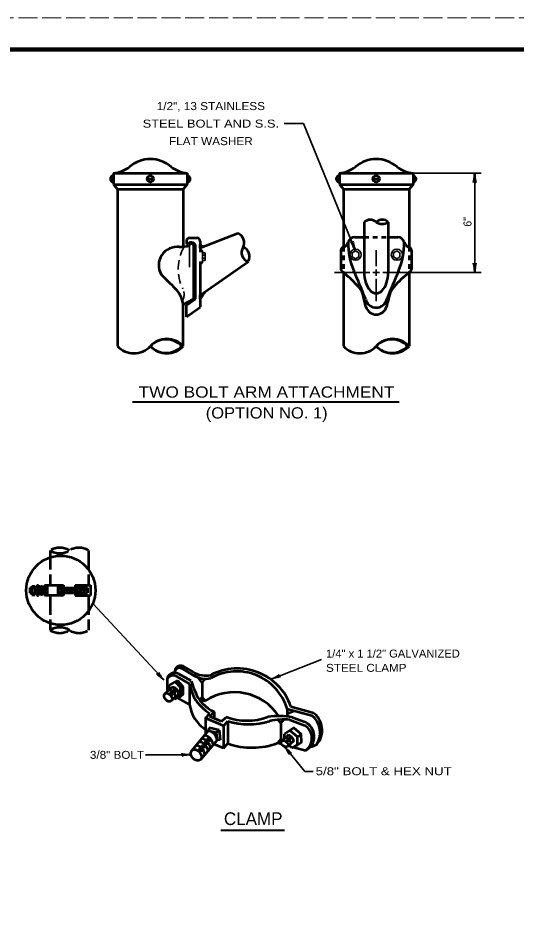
# Model space of a CAD drawing. Extents: x 6488 to 7168, y 276 to 716.
# Drawn here: x 6645 to 6801.8, y 436 to 716 of the extents above; entities that cross this region are included whole.
import ezdxf
from ezdxf.enums import TextEntityAlignment as Align

# ---------------------------------------------------------------- set-up
doc = ezdxf.new("R2010")
doc.units = 0
for name, pattern in [('LONG_DASHED', [7.5, 6, -1.5]), ('MEDIUM_DASHED', [4.5, 3, -1.5]), ('SHORT_DASHED', [2.7, 1.5, -1.2])]:
    doc.linetypes.add(name, pattern=pattern)
doc.layers.add('1', color=7, linetype='Continuous', lineweight=35)
doc.layers.add('61', color=7, linetype='Continuous', lineweight=35)

msp = doc.modelspace()

# ---------------------------------------------------------------- linework, layer by layer
at = {"layer": '1'}
for p, q in [((6728.799, 682.801), (6734.872, 682.801)), ((6751.122, 642.92), (6734.872, 682.801)), ((6769.322, 667.1), (6790.742, 667.1)), ((6788.742, 667.1), (6788.742, 635.86)), ((6698.982, 637.52), (6698.982, 644.38)), ((6700.122, 627.44), (6700.122, 644.06)), ((6703.122, 639.08), (6703.122, 642.44)), ((6751.242, 642.68), (6750.222, 642.06)), ((6750.222, 642.06), (6750.222, 640.8)), ((6751.242, 642.68), (6752.242, 642.06)), ((6752.242, 642.06), (6752.242, 640.8)), ((6757.742, 642.92), (6757.742, 637.86)), ((6764.222, 642.68), (6763.222, 642.06)), ((6763.222, 642.06), (6763.222, 640.8)), ((6764.222, 642.68), (6765.222, 642.06)), ((6765.222, 642.06), (6765.222, 640.8)), ((6703.882, 641.26), (6703.142, 641.26)), ((6703.882, 640.4), (6703.142, 640.4)), ((6703.882, 639.66), (6703.142, 639.66)), ((6744.642, 635.86), (6755.742, 635.86)), ((6756.702, 635.86), (6758.722, 635.86)), ((6757.742, 636.84), (6757.742, 634.84)), ((6759.782, 635.86), (6790.742, 635.86)), ((6757.742, 633.82), (6757.742, 626.78)), ((6668.533, 531.678), (6690.869, 507.577)), ((6724.751, 507.828), (6740.562, 513.979)), ((6699.435, 483.978), (6685.097, 483.978))]:
    msp.add_line(p, q, dxfattribs=at)
at = {"layer": '1', "lineweight": 53}
for p, q in [((6675.082, 667.1), (6698.262, 667.1)), ((6675.082, 667.1), (6675.082, 663.58)), ((6698.262, 667.1), (6698.262, 663.58)), ((6746.142, 667.1), (6769.322, 667.1)), ((6746.142, 667.1), (6746.142, 663.58)), ((6769.322, 667.1), (6769.322, 663.58)), ((6674.082, 665.34), (6674.822, 665.34)), ((6685.902, 665.34), (6687.422, 665.34)), ((6698.522, 665.34), (6699.222, 665.34)), ((6745.142, 665.34), (6745.902, 665.34)), ((6756.982, 665.34), (6758.482, 665.34)), ((6769.582, 665.34), (6770.282, 665.34)), ((6675.082, 663.58), (6698.262, 663.58)), ((6675.082, 663.58), (6676.342, 662.06)), ((6676.342, 662.06), (6676.342, 612.68)), ((6676.342, 662.06), (6697.002, 662.06)), ((6698.262, 663.58), (6697.002, 662.06)), ((6697.002, 662.06), (6697.002, 643.92)), ((6746.142, 663.58), (6769.322, 663.58)), ((6746.142, 663.58), (6747.402, 662.06)), ((6747.402, 662.06), (6768.062, 662.06)), ((6747.402, 662.06), (6747.402, 643.92)), ((6769.322, 663.58), (6768.062, 662.06)), ((6768.062, 662.06), (6768.062, 643.92)), ((6753.962, 651.74), (6753.962, 635.86)), ((6761.522, 651.74), (6761.522, 635.86)), ((6702.362, 643.64), (6714.222, 648.18)), ((6750.882, 646.98), (6753.962, 646.98)), ((6761.522, 646.98), (6764.582, 646.98)), ((6698.022, 645.76), (6698.022, 644.72)), ((6698.022, 644.72), (6698.522, 644.72)), ((6699.022, 646.76), (6701.362, 646.76)), ((6702.362, 645.76), (6702.362, 645.24)), ((6702.362, 645.24), (6702.362, 642.2)), ((6700.902, 627.58), (6700.902, 643.76)), ((6746.642, 642.92), (6746.642, 636.86)), ((6768.822, 642.92), (6768.822, 636.86)), ((6702.362, 639.32), (6702.362, 629.74)), ((6702.362, 628.68), (6717.502, 639.28)), ((6747.402, 635.86), (6747.402, 612.68)), ((6768.062, 635.86), (6768.062, 612.68)), ((6697.002, 625.78), (6700.122, 627.44)), ((6698.022, 625.56), (6700.902, 627.58)), ((6702.362, 629.74), (6702.362, 624.9)), ((6697.002, 612.68), (6697.002, 625.78)), ((6698.022, 621.86), (6698.022, 625.56)), ((6698.022, 621.86), (6702.362, 624.9)), ((6648.782, 536.53), (6648.782, 535.01)), ((6648.782, 536.53), (6653.322, 536.53)), ((6648.782, 535.01), (6653.322, 535.01)), ((6649.082, 535.91), (6649.082, 535.61)), ((6649.382, 537.13), (6649.382, 534.41)), ((6649.382, 537.13), (6650.302, 537.13)), ((6650.302, 537.13), (6650.302, 534.41)), ((6650.902, 537.43), (6650.902, 534.11)), ((6650.902, 537.43), (6651.502, 537.43)), ((6651.502, 537.43), (6651.502, 534.11)), ((6652.122, 537.13), (6652.122, 534.41)), ((6652.122, 537.13), (6652.722, 537.13)), ((6652.722, 537.13), (6652.722, 534.41)), ((6653.322, 537.43), (6653.322, 534.11)), ((6653.322, 537.43), (6659.362, 537.43)), ((6654.222, 537.43), (6654.222, 534.11)), ((6657.562, 536.83), (6658.762, 536.83)), ((6657.562, 536.83), (6657.562, 534.71)), ((6657.862, 536.23), (6658.762, 536.23)), ((6657.862, 535.31), (6658.762, 535.31)), ((6658.762, 537.43), (6658.762, 534.11)), ((6659.362, 537.43), (6659.362, 534.11)), ((6659.822, 536.07), (6659.822, 535.47)), ((6660.282, 536.53), (6660.282, 535.01)), ((6660.722, 536.07), (6660.722, 535.47)), ((6661.182, 536.53), (6661.182, 535.01)), ((6661.642, 536.07), (6661.642, 535.47)), ((6662.102, 536.53), (6662.102, 535.01)), ((6662.542, 536.07), (6662.542, 535.47)), ((6663.002, 537.43), (6663.002, 534.11)), ((6663.002, 537.43), (6667.842, 537.43)), ((6663.602, 537.43), (6663.602, 534.11)), ((6664.822, 536.83), (6663.622, 536.83)), ((6664.522, 536.23), (6663.622, 536.23)), ((6664.522, 535.31), (6663.622, 535.31)), ((6664.822, 535.61), (6664.522, 535.31)), ((6664.522, 535.31), (6664.822, 535.01)), ((6664.822, 536.83), (6664.822, 534.71)), ((6665.342, 536.07), (6665.342, 535.47)), ((6665.882, 536.53), (6665.882, 535.01)), ((6666.402, 536.07), (6666.402, 535.47)), ((6666.922, 536.53), (6666.922, 535.01)), ((6667.842, 537.43), (6667.842, 534.11)), ((6649.382, 534.41), (6650.302, 534.41)), ((6650.902, 534.11), (6651.502, 534.11)), ((6652.722, 534.41), (6652.122, 534.41)), ((6659.362, 534.11), (6653.322, 534.11)), ((6657.562, 534.71), (6658.762, 534.71)), ((6663.002, 534.11), (6667.842, 534.11)), ((6664.822, 534.71), (6663.622, 534.71)), ((6700.179, 510.074), (6696.959, 511.914)), ((6700.179, 509.114), (6696.959, 510.934)), ((6691.919, 507.834), (6691.919, 503.814)), ((6695.259, 507.354), (6692.579, 505.934)), ((6694.499, 506.954), (6696.119, 505.154)), ((6699.039, 506.354), (6695.019, 508.654)), ((6699.539, 507.234), (6695.519, 509.514)), ((6702.979, 506.694), (6701.699, 508.334)), ((6702.979, 506.694), (6703.939, 507.934)), ((6693.479, 505.234), (6691.219, 503.194)), ((6692.579, 504.434), (6692.579, 505.934)), ((6699.039, 506.354), (6699.039, 499.794)), ((6695.499, 502.974), (6693.259, 500.954)), ((6694.099, 501.734), (6694.299, 501.494)), ((6699.039, 499.794), (6695.239, 501.954)), ((6702.979, 502.154), (6703.919, 500.974)), ((6702.499, 501.154), (6703.919, 500.974)), ((6729.699, 498.474), (6737.479, 496.374)), ((6729.699, 498.474), (6729.699, 496.054)), ((6730.919, 499.174), (6737.739, 497.354)), ((6704.059, 495.514), (6705.419, 497.014)), ((6705.379, 496.054), (6706.739, 497.554)), ((6709.099, 494.474), (6705.379, 496.054)), ((6706.739, 497.554), (6706.739, 495.474)), ((6709.099, 494.474), (6710.519, 495.894)), ((6729.819, 497.014), (6731.899, 497.874)), ((6731.459, 495.774), (6735.239, 494.334)), ((6709.639, 493.154), (6704.059, 495.514)), ((6704.059, 495.514), (6704.059, 490.534)), ((6709.639, 493.154), (6711.059, 494.574)), ((6709.639, 493.154), (6709.639, 486.094)), ((6711.059, 494.574), (6711.059, 487.514)), ((6727.739, 493.954), (6726.899, 495.014)), ((6727.739, 493.954), (6728.619, 495.094)), ((6727.739, 493.954), (6727.739, 488.914)), ((6730.579, 494.994), (6735.299, 493.194)), ((6704.899, 491.534), (6699.719, 485.354)), ((6705.139, 492.514), (6704.899, 491.534)), ((6707.399, 490.914), (6704.899, 491.534)), ((6708.319, 491.734), (6705.139, 492.514)), ((6708.319, 491.734), (6707.399, 490.914)), ((6707.399, 490.914), (6707.659, 488.614)), ((6708.319, 491.734), (6708.659, 488.734)), ((6730.099, 490.274), (6727.879, 488.214)), ((6728.919, 489.174), (6728.879, 490.534)), ((6732.919, 489.654), (6730.599, 491.594)), ((6707.659, 488.614), (6702.459, 482.434)), ((6709.639, 486.094), (6706.619, 487.374)), ((6708.659, 488.734), (6707.659, 488.614)), ((6709.639, 486.094), (6711.059, 487.514)), ((6727.739, 488.914), (6726.799, 487.714)), ((6726.799, 487.714), (6727.899, 487.414)), ((6727.739, 488.914), (6728.119, 488.414)), ((6731.819, 488.434), (6729.979, 486.714)), ((6731.219, 486.174), (6730.259, 486.974)), ((6731.679, 486.414), (6735.559, 485.374))]:
    msp.add_line(p, q, dxfattribs=at)
at = {"layer": '1', "linetype": 'SHORT_DASHED', "lineweight": 53}
for p, q in [((6753.962, 646.98), (6761.522, 646.98)), ((6747.402, 643.92), (6747.402, 635.86)), ((6768.062, 643.92), (6768.062, 635.86))]:
    msp.add_line(p, q, dxfattribs=at)
at = {"layer": '1', "lineweight": 40}
for p, q in [((6681.102, 595.14), (6764.982, 595.14)), ((6708.814, 460.253), (6728.892, 460.253))]:
    msp.add_line(p, q, dxfattribs=at)
at = {"layer": '1', "linetype": 'LONG_DASHED', "lineweight": 53}
for p, q in [((6655.142, 548.31), (6655.142, 537.43)), ((6667.242, 548.31), (6667.242, 537.43)), ((6655.142, 534.11), (6655.142, 523.21)), ((6667.242, 534.11), (6667.242, 523.21))]:
    msp.add_line(p, q, dxfattribs=at)
at = {"layer": '1', "lineweight": 53}
for points in [[(6703.462, 644.06), (6702.362, 643.64), (6702.362, 644.68)], [(6702.382, 627.44), (6702.382, 628.7), (6704.042, 629.88)], [(6657.562, 536.53), (6657.862, 536.23), (6657.562, 535.91)], [(6657.562, 535.61), (6657.862, 535.31), (6657.562, 535.01)], [(6659.362, 536.53), (6660.282, 536.53), (6661.182, 536.53), (6662.102, 536.53), (6663.002, 536.53)], [(6659.362, 535.01), (6661.182, 535.01), (6663.002, 535.01)], [(6664.822, 536.53), (6664.522, 536.23), (6664.822, 535.91)], [(6664.822, 536.53), (6665.882, 536.53), (6666.922, 536.53)], [(6664.822, 535.01), (6665.882, 535.01), (6666.922, 535.01)], [(6695.259, 507.354), (6696.939, 505.494), (6696.939, 502.974), (6696.119, 502.394), (6694.299, 501.494)], [(6696.119, 502.394), (6696.119, 505.154), (6696.939, 505.494)], [(6702.979, 506.694), (6702.979, 502.154), (6702.339, 501.354)], [(6731.219, 486.174), (6732.999, 487.134), (6734.239, 487.994), (6734.159, 490.514), (6731.839, 492.454), (6728.879, 490.534)], [(6732.999, 487.134), (6732.919, 489.654), (6734.159, 490.514)]]:
    msp.add_lwpolyline(points, dxfattribs=at)
at = {"layer": '1'}
for points in [[(6703.882, 639.66), (6703.882, 642.02), (6703.142, 642.02)], [(6752.242, 640.8), (6751.242, 640.16), (6750.222, 640.8)], [(6765.222, 640.8), (6764.222, 640.16), (6763.222, 640.8)], [(6728.898, 486.568), (6735.292, 478.706), (6737.927, 478.706)]]:
    msp.add_lwpolyline(points, dxfattribs=at)
at = {"layer": '1', "lineweight": 53}
for centre, radius in [((6686.667, 665.34), 1.008), ((6757.731, 665.34), 1.008), ((6658.497, 535.774), 10.886)]:
    msp.add_circle(centre, radius, dxfattribs=at)
at = {"layer": '1'}
for centre in [(6751.248, 641.454), (6764.227, 641.446)]:
    msp.add_circle(centre, 1.764, dxfattribs=at)
at = {"layer": '1', "lineweight": 53}
for centre, radius, start, end in [((6686.673, 661.531), 10.025, 49.18722, 130.81278), ((6757.737, 661.531), 10.025, 49.18722, 130.81278), ((6674.151, 676.735), 9.678, 275.5142, 308.08862), ((6699.195, 676.735), 9.678, 231.91138, 264.4858), ((6745.215, 676.735), 9.678, 275.5142, 308.08862), ((6770.259, 676.735), 9.678, 231.91138, 264.4858), ((6675.087, 665.312), 1.008, 90.3199, 269.6801), ((6698.218, 665.312), 1.008, 272.67956, 87.32044), ((6746.151, 665.312), 1.008, 90.3199, 269.6801), ((6769.282, 665.312), 1.008, 272.67956, 87.32044), ((6755.847, 649.542), 2.891, 49.17959, 130.82041), ((6759.627, 649.649), 2.812, 47.76241, 132.23758), ((6759.627, 654.476), 3.333, 235.45601, 304.54399), ((6712.915, 645.177), 3.282, 333.96531, 66.42353), ((6751.02, 644.782), 2.2, 93.41837, 162.8601), ((6764.455, 644.782), 2.2, 17.1399, 86.58162), ((6696.073, 652.427), 8.553, 268.07998, 289.90391), ((6699.021, 645.755), 1.008, 90, 180), ((6699.611, 643.99), 1.312, 350.09958, 146.42495), ((6701.356, 645.755), 1.008, 0, 90), ((6703.777, 645.898), 1.866, 221.01419, 260.32206), ((6746.746, 645.959), 2.235, 294.0674, 346.32146), ((6771.756, 645.164), 22.84, 179.33091, 202.67617), ((6743.719, 645.164), 22.84, 337.32383, 0.66909), ((6768.729, 645.959), 2.235, 193.67854, 245.9326), ((6695.102, 638.114), 5.805, 83.22236, 210.1126), ((6718.267, 642.095), 2.91, 145.65086, 254.73799), ((6714.611, 640.856), 3.282, 333.96531, 66.42353), ((6747.714, 642.853), 1.067, 93.07015, 176.92984), ((6767.76, 642.853), 1.067, 3.07016, 86.92985), ((6747.714, 636.919), 1.067, 183.07016, 253.15341), ((6720.251, 603.149), 42.543, 42.29957, 50.33685), ((6568.182, 554.45), 200.037, 21.39177, 24.17121), ((6951.517, 552.676), 204.618, 155.85991, 158.57712), ((6795.223, 603.149), 42.543, 129.66315, 138.49633), ((6767.76, 636.919), 1.067, 286.84659, 356.92984), ((7805.326, 1750.591), 1577.297, 225.00367, 225.22952), ((6688.926, 624.885), 8.128, 6.28285, 46.84726), ((6748.598, 627.807), 5.052, 9.48157, 51.86654), ((6767.078, 627.474), 5.329, 133.87214, 169.50589), ((6710.958, 623.346), 9.51, 136.62273, 154.46868), ((6675.522, 606.627), 81.104, 13.13509, 15.74771), ((6757.737, 628.174), 3.386, 193.00171, 346.99829), ((6839.953, 606.627), 81.104, 163.98892, 166.86491), ((6757.737, 625.968), 3.36, 195.72161, 344.27839), ((6691.839, 607.854), 7.063, 42.99091, 137.00909), ((6691.579, 607.981), 6.786, 43.44505, 136.28697), ((6762.903, 607.854), 7.063, 42.99091, 137.00909), ((6762.643, 607.981), 6.786, 43.44505, 136.28697), ((6681.507, 617.486), 7.063, 222.99091, 317.00909), ((6691.839, 617.486), 7.063, 222.99091, 317.00909), ((6691.6, 617.326), 6.779, 223.38031, 316.35171), ((6752.571, 617.486), 7.063, 222.99091, 317.00909), ((6762.903, 617.486), 7.063, 222.99091, 317.00909), ((6762.664, 617.326), 6.779, 223.38031, 316.35171), ((6694.333, 507.361), 2.464, 61.16852, 169.07366), ((6696.262, 510.077), 1.967, 68.98454, 184.96528), ((6695.905, 509.73), 1.613, 48.79801, 173.73367), ((6704.074, 516.05), 7.131, 236.83956, 283.32479), ((6714.037, 493.271), 17.892, 19.29143, 117.70819), ((6713.827, 493.697), 16.566, 16.7434, 119.30902), ((6693.826, 506.869), 2.14, 56.06469, 153.37669), ((6720.612, 512.954), 21.84, 195.21089, 204.37149), ((6704.022, 514.783), 6.854, 235.84201, 284.32234), ((6692.648, 502.453), 1.909, 349.61263, 94.38617), ((6693.62, 503.323), 1.909, 349.61263, 94.38617), ((6693.244, 502.994), 1.742, 20.88408, 69.09679), ((6711.687, 508.143), 12.777, 188.06983, 240.59731), ((6692.192, 502.067), 1.742, 20.88408, 69.09679), ((6711.867, 508.402), 12.008, 201.80286, 244.70416), ((6713.072, 486.783), 16.89, 33.86522, 122.8499), ((6709.752, 501.171), 10.803, 187.30417, 238.23787), ((6717.076, 514.154), 19.396, 250.25742, 289.74258), ((6727.212, 474.447), 21.748, 78.72641, 99.48511), ((6733.153, 490.957), 6.939, 327.83586, 51.43283), ((6733.979, 491.748), 6.752, 318.38164, 56.15447), ((6717.61, 516.375), 22.763, 253.27137, 286.72862), ((6728.644, 475.321), 19.77, 84.35687, 103.10294), ((6733.254, 489.771), 4.969, 297.71146, 66.56345), ((6732.821, 489.19), 4.701, 305.70046, 58.26699), ((6703.247, 486.924), 3.193, 4.32722, 81.54855), ((6704.468, 488.36), 3.193, 4.65558, 82.27962), ((6729.458, 487.95), 2.406, 11.41742, 74.57891), ((6701.658, 484.847), 3.193, 7.29827, 83.92311), ((6702.422, 485.916), 3.193, 4.74535, 82.35434), ((6703.108, 486.603), 1.531, 14.18506, 70.66849), ((6703.902, 487.673), 1.531, 14.18506, 70.66849), ((6718.651, 509.525), 23.278, 250.96338, 290.4942), ((6728.592, 487.125), 2.406, 11.41742, 74.57891), ((6728.836, 487.435), 1.432, 21.50211, 64.13038), ((6729.712, 488.237), 1.432, 21.50211, 64.13038), ((6736.852, 490.31), 3.743, 273.11257, 305.52158), ((6700.651, 483.778), 3.193, 5.19441, 82.73082), ((6701.275, 484.465), 1.531, 14.18506, 70.66849), ((6702.252, 485.565), 1.531, 14.18506, 70.66849)]:
    msp.add_arc(centre, radius, start, end, dxfattribs=at)
at = {"layer": '1'}
for centre, radius, start, end in [((6699.538, 644.172), 0.593, 349.37883, 158.91973), ((6702.406, 642.274), 0.738, 13.64106, 87.59419), ((6702.406, 639.246), 0.738, 272.40581, 346.35894)]:
    msp.add_arc(centre, radius, start, end, dxfattribs=at)
at = {"layer": '1', "linetype": 'MEDIUM_DASHED'}
for centre, radius, start, end in [((6709.666, 636.948), 14.228, 150.47291, 206.06704), ((6693.269, 628.929), 4.026, 330.81735, 26.04877)]:
    msp.add_arc(centre, radius, start, end, dxfattribs=at)
at = {"layer": '1', "linetype": 'LONG_DASHED', "lineweight": 53}
for centre, start, end in [((6658.162, 543.585), 57.42639, 122.57361), ((6664.21, 543.585), 57.42639, 122.57361), ((6658.162, 553.052), 237.42639, 302.57361), ((6658.162, 518.486), 57.42639, 122.57361), ((6658.162, 527.953), 237.42639, 302.57361), ((6664.21, 527.953), 237.42639, 302.57361)]:
    msp.add_arc(centre, 5.617, start, end, dxfattribs=at)
at = {"layer": '1', "lineweight": 40}
for centre, major_axis, ratio, start_param, end_param in [((6788.52, 665.973), (0.177, 1.77), 0.07063, 3.1407148, 5.41811), ((6789.012, 666.002), (-0.157, 1.8), 0.122415, 0.8963533, 3.1415927), ((6750.444, 643.832), (0.824, -1.608), 0.122415, 0.8963533, 3.1415927), ((6750.888, 644.045), (-0.503, 1.707), 0.07063, 6.2823074, 8.5597026), ((6788.455, 636.954), (0.157, -1.8), 0.122415, 0.8963533, 3.1415927), ((6788.947, 636.984), (-0.177, -1.77), 0.07063, 3.1407148, 5.41811), ((6690.263, 508.543), (1.065, -1.408), 0.07063, 3.1407148, 5.41811), ((6689.925, 508.19), (1.328, -1.204), 0.122415, 0.8963533, 3.1415927), ((6725.668, 508.481), (-1.608, -0.793), 0.122415, 0.8963533, 3.1415927), ((6725.668, 508.481), (-1.608, -0.793), 0.122415, 0.8963533, 3.1415927), ((6725.872, 508.037), (-1.701, -0.473), 0.07063, 3.1407148, 5.41811), ((6725.872, 508.037), (-1.701, -0.473), 0.07063, 3.1407148, 5.41811), ((6729.44, 485.565), (0.972, -1.474), 0.07063, 6.2823074, 8.5597026), ((6729.44, 485.565), (0.972, -1.474), 0.07063, 6.2823074, 8.5597026), ((6729.801, 485.896), (-1.248, 1.287), 0.122415, 0.8963533, 3.1415927), ((6729.801, 485.896), (-1.248, 1.287), 0.122415, 0.8963533, 3.1415927), ((6698.344, 483.702), (1.786, 0.156), 0.122415, 0.8963533, 3.1415927), ((6698.344, 483.702), (1.786, 0.156), 0.122415, 0.8963533, 3.1415927), ((6698.314, 484.189), (1.756, -0.176), 0.07063, 3.1407148, 5.41811), ((6698.314, 484.189), (1.756, -0.176), 0.07063, 3.1407148, 5.41811)]:
    msp.add_ellipse(centre, major_axis=major_axis, ratio=ratio, start_param=start_param, end_param=end_param, dxfattribs=at)
at = {"layer": '1', "lineweight": 53}
msp.add_ellipse((6757.737, 635.854), major_axis=(0, 6.553), ratio=0.576878, start_param=1.5707963, end_param=4.712389, dxfattribs=at)
for centre, major_axis, ratio in [((6692.239, 502.079), (1.012, -1.124), 0.663346), ((6728.929, 487.458), (1.044, -0.75), 0.624582), ((6701.091, 483.895), (1.377, -1.452), 0.71432)]:
    msp.add_ellipse(centre, major_axis=major_axis, ratio=ratio, dxfattribs=at)
at = {"layer": '61', "linetype": 'LONG_DASHED', "lineweight": 13}
msp.add_line((6487.643, 716.04), (7167.663, 716.04), dxfattribs=at)
at = {"layer": '61', "lineweight": 158}
msp.add_lwpolyline([(7156.683, 706.04), (6517.643, 706.04), (6517.643, 286.02)], dxfattribs=at)

# ---------------------------------------------------------------- texts
at = {"layer": '1'}
for s, height, width, p in [('1/2", 13 STAINLESS', 2.52, 1.1, (6705.712, 686.981)), ('STEEL BOLT AND S.S.', 2.52, 1.2, (6705.712, 681.461)), ('FLAT WASHER', 2.52, 1.1, (6705.712, 675.941)), ('TWO BOLT ARM ATTACHMENT', 3.528, 1.15, (6723.222, 596.44)), ('(OPTION NO. 1)', 3.528, 1.1, (6723.27, 589.88))]:
    msp.add_text(s, height=height, dxfattribs=dict(at, width=width)).set_placement(p, align=Align.CENTER)
msp.add_text('6"', height=2.52, rotation=90, dxfattribs=at).set_placement((6787.722, 650.26))
for s, width, p in [('1/4" x 1 1/2" GALVANIZED', 1.05, (6741.943, 514.617)), ('STEEL CLAMP', 1.1, (6741.943, 510.117)), ('3/8" BOLT', 1.1, (6667.654, 482.723)), ('5/8" BOLT & HEX NUT', 1.25, (6738.68, 477.576))]:
    msp.add_text(s, height=2.5, dxfattribs=dict(at, width=width)).set_placement(p)
msp.add_text('CLAMP', height=4, dxfattribs=at).set_placement((6709.818, 461.885))

doc.saveas('drawing.dxf')
